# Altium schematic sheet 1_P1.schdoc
size 309 x 223 mm; Symbol: Sheet-Symbol_A4; Device: Sheet-Symbol_A4; @Page Name: P1; @Create Date: 2023-06-11; @Page Count: 1; @Page No: 1; @Project Name: 工业检测; @Schematic Name: Schematic1; @Update Date: 2023-06-11; Company: 嘉立创EDA; Page Size: A4; Version: V1.0
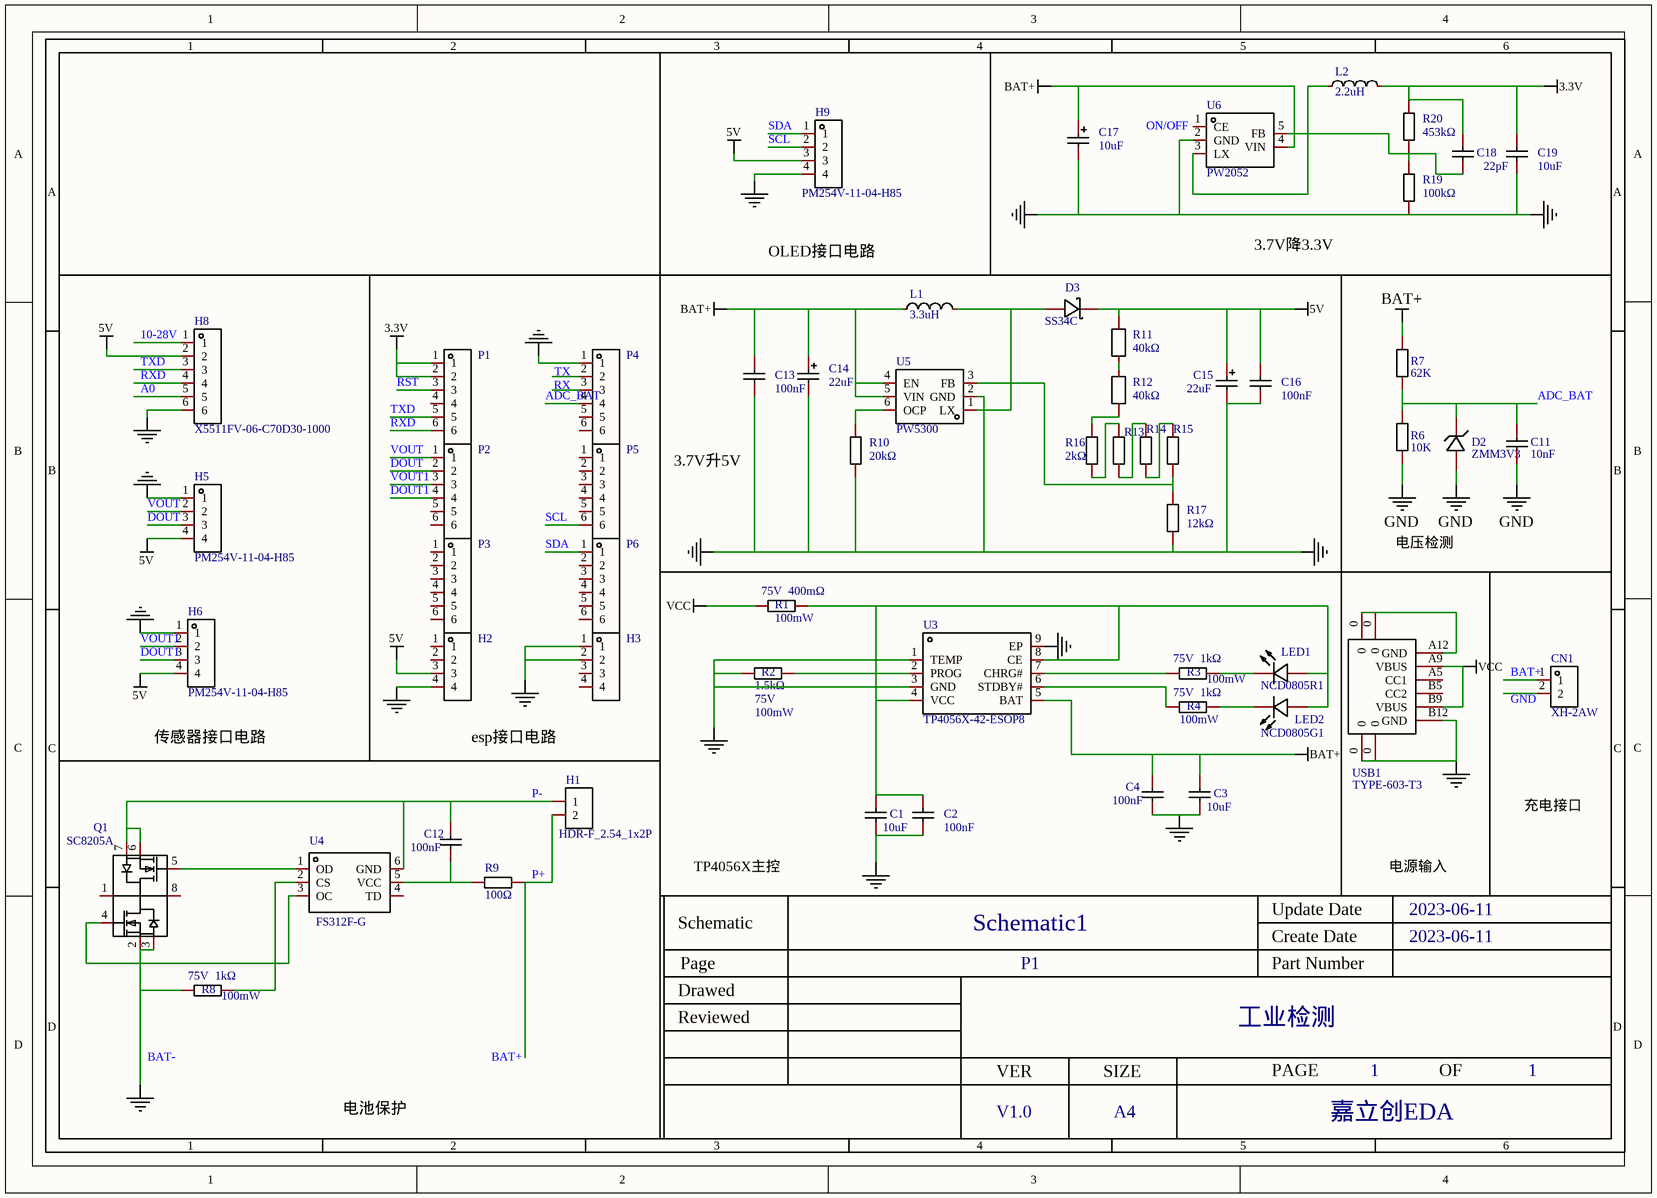
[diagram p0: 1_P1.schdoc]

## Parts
C1  10uF  [C1206]
C2  100nF  [C0603]
C3  10uF  [C1206]
C4  100nF  [C0603]
C11  10nF  [C0603]
C12  100nF  [C0603]
C13  100nF  [C0603]
C14  22uF  [CASE-B_3528]
C15  22uF  [CASE-B_3528]
C16  100nF  [C0603]
C17  10uF  [CAP-SMD_L3.5-W2.8-R-RD]
C18  22pF  [C0603]
C19  10uF  [C1206]
CN1  XH-2AW  [CONN-TH_XH-2AW_C2908611]
D2  ZMM3V3  [LL-34_L3.5-W1.5-RD]
D3  SS34C  [SMC_L7.1-W6.2-LS8.1-R-RD]
H1  HDR-F_2.54_1x2P  [HDR-TH_2P-P2.54-V-F]
H2  2.54-1*4P母  [HDR-TH_4P-P2.54-V-F]  (value not drawn)
H3  2.54-1*4P母  [HDR-TH_4P-P2.54-V-F]  (value not drawn)
H5  PM254V-11-04-H85  [HDR-TH_4P-P2.54-V-F]
H6  PM254V-11-04-H85  [HDR-TH_4P-P2.54-V-F]
H8  X5511FV-06-C70D30-1000  [HDR-TH_6P-P2.54-V-F-3]
H9  PM254V-11-04-H85  [HDR-TH_4P-P2.54-V-F]
L1  3.3uH  [IND-SMD_L5.4-W5.2]
L2  2.2uH  [IND-SMD_L4.4-W4.2]
LED1  NCD0805R1  [LED0805-RD_RED]
LED2  NCD0805G1  [LED0805-R-RD]
P1  2.54-1*6P母  [HDR-TH_6P-P2.54-V-F]  (value not drawn)
P2  2.54-1*6P母  [HDR-TH_6P-P2.54-V-F]  (value not drawn)
P3  2.54-1*6P母  [HDR-TH_6P-P2.54-V-F]  (value not drawn)
P4  2.54-1*6P母  [HDR-TH_6P-P2.54-V-F]  (value not drawn)
P5  2.54-1*6P母  [HDR-TH_6P-P2.54-V-F]  (value not drawn)
P6  2.54-1*6P母  [HDR-TH_6P-P2.54-V-F]  (value not drawn)
Q1  SC8205A  [TSSOP-8_L4.4-W3.0-P0.65-LS6.4-BL]
R1  Power(Watts): 100mW  Overload Voltage (Max): 75V  [R0603]  (hidden comment: 400mΩ)
R2  Power(Watts): 100mW  Overload Voltage (Max): 75V  [R0603]  (hidden comment: 1.5kΩ)
R3  Power(Watts): 100mW  Overload Voltage (Max): 75V  [R0603]  (hidden comment: 1kΩ)
R4  Power(Watts): 100mW  Overload Voltage (Max): 75V  [R0603]  (hidden comment: 1kΩ)
R6  10K  [R0603]
R7  62K  [R0603]
R8  Power(Watts): 100mW  Overload Voltage (Max): 75V  [R0603]  (hidden comment: 1kΩ)
R9  100Ω  [R0603]
R10  20kΩ  [R0603]
R11  40kΩ  [R0603]
R12  40kΩ  [R0603]
R13  2kΩ  [R0603]  (value not drawn)
R14  2kΩ  [R0603]  (value not drawn)
R15  2kΩ  [R0603]  (value not drawn)
R16  2kΩ  [R0603]
R17  12kΩ  [R0603]
R19  100kΩ  [R0603]
R20  453kΩ  [R0603]
U3  TP4056X-42-ESOP8  [SOP-8_L4.9-W3.9-P1.27-LS6.0-TL-EP]
U4  FS312F-G  [SOT-23-6_L2.9-W1.6-P0.95-LS2.8-BR]
U5  PW5300  [SOT-23-6_L2.9-W1.6-P0.95-LS2.8-BL]
U6  PW2052  [SOT-23-5_L2.9-W1.6-P0.95-LS2.8-BL]
USB1  TYPE-603-T3  [USB-C-SMD_TYPE-603-T3]

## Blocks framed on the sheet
OLED接口电路: H9
3.7V降3.3V: C17-C19 L2 R19 R20 U6
传感器接口电路: H5 H6 H8
esp接口电路: H2 H3 P1-P6
3.7V升5V: C13-C16 D3 L1 R10-R17 U5
电压检测: C11 D2 R6 R7
TP4056X主控: C1-C4 LED1 LED2 R1-R4 U3
电源输入: USB1
充电接口: CN1
电池保护: C12 H1 Q1 R8 R9 U4

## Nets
3.3V: C18.2 C19.2 L2.2 P1.1 P1.2 R20.2
5V: C15.1 C16.2 D3.2(K) H2.3 H5.4 H6.4 H8.2 H9.3 R11.2
BAT+: C3.2 C4.2 C13.2 C14.1 C17.1 L1.1 R7.2 U3.5(BAT) U5.4(EN) U5.5(VIN) U6.4(VIN)
GND: C11.1 D2.2(A) R6.1
NetC1_1: C1.1 C2.1 C3.1 C4.1 C13.1 C14.2 C15.2 C16.1 C17.2 C19.1 H2.4 H3.1 H3.2 H5.1 H6.1 H8.6 H9.4 P4.1 Q1.2(S1) Q1.3(S1) R2.1 R8.1 R10.1 R17.1 R19.1 U3.1(TEMP) U3.3(GND) U3.9(EP) U5.2(GND) U6.2(GND) USB1.0 USB1.B12(GND)
VCC: R1.1 USB1.A9(VBUS) USB1.B9(VBUS)
ADC_BAT: C11.2 D2.1(C) P4.4 R6.2 R7.1
DOUT: P2.2
DOUT1: P2.4
RXD: P1.6
SCL: P5.6
SDA: P6.1
TXD: P1.5
VOUT: P2.1
VOUT1: P2.3
NetC1_2: C1.2 C2.2 LED1.2(+) LED2.1(A) R1.2 U3.4(VCC) U3.8(CE)
NetC12_1: C12.1 R9.1 U4.5(VCC)
NetC12_2: C12.2 H1.1 Q1.6(S2) Q1.7(S2) U4.6(GND)
NetC18_1: C18.1 R19.2 R20.1 U6.5(FB)
NetD3_1: D3.1(A) L1.2 U5.1(LX)
NetH1_2: H1.2 R9.2
NetL2_1: L2.1 U6.3(LX)
NetLED1_1: LED1.1(-) R3.2
NetLED2_2: LED2.2(K) R4.2
NetQ1_4: Q1.4(G1) U4.3(OC)
NetQ1_5: Q1.5(G2) U4.1(OD)
NetR2_2: R2.2 U3.2(PROG)
NetR3_1: R3.1 U3.7(CHRG#)
NetR4_1: R4.1 U3.6(STDBY#)
NetR8_2: R8.2 U4.2(CS)
NetR10_2: R10.2 U5.6(OCP)
NetR11_1: R11.1 R12.2
NetR12_1: R12.1 R16.2
NetR13_1: R13.1 R14.2
NetR13_2: R13.2 R16.1
NetR14_1: R14.1 R15.2
NetR15_1: R15.1 R17.2 U5.3(FB)
NetUSB1_0: USB1.0 USB1.A12(GND)

Not connected (* = marked no-connect by the designer): CN1 1 2; H2 1 2; H3 3 4; H5 2 3; H6 2 3; H8 1 3 4 5; H9 1 2; P1 3 4; P2 5 6; P3 1 2 3 4 5 6; P4 2 3 5 6; P5 1 2 3 4 5; P6 2 3 4 5 6; Q1 1(D12) 8(D12); U4 4(TD); U6 1(CE); USB1 A5(CC1) B5(CC2)

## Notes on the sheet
- (near H9) SDA
- (near H9) SCL
- (near U6) ON/OFF
- (near H8) 10-28V
- (near H8) A0
- (near H8) TXD
- (near H8) RXD
- (near P1) RST
- (near P4) TX
- (near P4) RX
- (near H5) VOUT
- (near H5) DOUT
- (near H6) VOUT1
- (near H6) DOUT1
- (near CN1) BAT+
- (near CN1) GND
- (near H1) P-
- (near R9) P+
- BAT-
- BAT+

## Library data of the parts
C1 C3 C19 = CL31A106KBHNNNE: 容值:10uF;精度:±10%;额定电压:50V;材质(温度系数):X5R;; Manufacturer: SAMSUNG(三星); Add into BOM: yes; Tolerance: ±10%; Voltage Rated: 50V; Temperature Coefficient: X5R
C2 C4 C12 C13 C16 = CC0603KRX7R8BB104: 容值:100nF;精度:±10%;额定电压:25V;材质(温度系数):X7R;; Manufacturer: YAGEO(国巨); Add into BOM: yes; Tolerance: ±10%; Voltage Rated: 25V; Temperature Coefficient: X7R
C11 = 0603B103K500NT: Manufacturer: FH; Convert to PCB: yes
C14 C15 = TAJB226K016RNJ: 容值:22uF;精度:±10%;额定电压:16V;等效串联电阻:2.3Ω@100kHz;工作温度:-55℃~+125℃;; Manufacturer: Kyocera AVX; Add into BOM: yes; Tolerance: ±10%; Rated Voltage: 16V
C17 = TAJB106K025RNJ: 容值:10uF;精度:±10%;额定电压:25V;等效串联电阻:2.5Ω@100kHz;; Manufacturer: Kyocera AVX; Add into BOM: yes; Tolerance: ±10%; Rated Voltage: 25V
C18 = CL10C220JB8NNNC: 容值:22pF;精度:±5%;额定电压:50V;材质(温度系数):C0G;; Manufacturer: SAMSUNG(三星); Add into BOM: yes; Tolerance: ±5%; Voltage Rated: 50V; Temperature Coefficient: C0G
CN1 = XH-2AW_C2908611: 参考系列:XH;间距:2.54mm;插针结构:1x2P;排数:1;每排PIN数:2;行距:-;公母:公型插针;安装方式:弯插;额定电流:3A;工作温度范围:-25℃~+85℃;; Manufacturer: HCTL(华灿天禄); Add into BOM: yes; Reference Series: XH; Pitch: 2.54mm; Pins Structure: 1x2P; Number of PINs Per Row: 2; Gender: 公型插针; Current Rating (Max): 3A
D2 = ZMM3V3: Manufacturer: SEMTECH; Convert to PCB: yes
D3 = SS34C_C13763: 直流反向耐压(Vr):40V;平均整流电流(Io):3A;正向压降(Vf):500mV@3A;; Manufacturer: MDD; Symbol: SS34; Add into BOM: yes; Reverse Voltage (Vr): 40V; Average Rectified Current (Io): 3A
H1 = HDR-F_2.54_1x2P: Symbol: Header-Female-2.54_1x2; Convert to PCB: yes
H2 H3 = 2.54-1*4P母: 排数:单排;总孔位数:4;间距:2.54mm;插孔结构:1x4P;行距:-;安装类型:直插;圆孔/方孔:方孔;额定电流:3A;额定电压:-;插孔方向:顶部;塑高:-;触头材质:青铜;触头镀层:-;工作温度范围:-40℃~+105℃;焊接温度(最大值):-;; Manufacturer: BOOMELE(博穆精密); Add into BOM: yes; Number of Holes: 4; Pitch: 2.54mm; Holes Structure: 1x4P; Circular Hole / Square Hole: 方孔; Current Rating (Max): 3A; Holes Direction: 顶部
H5 H6 H9 = PM254V-11-04-H85: 排数:单排;总孔位数:4;间距:2.54mm;插孔结构:1x4P;行距:-;安装类型:直插;塑高:-;触头材质:黄铜;触头镀层:-;; Manufacturer: XFCN(兴飞); Add into BOM: yes; Number of Holes: 4; Pitch: 2.54mm; Holes Structure: 1x4P
H8 = X5511FV-06-C70D30-1000: 排数:单排;总孔位数:6;间距:2.54mm;插孔结构:1x6P;行距:-;安装类型:直插;圆孔/方孔:圆孔;额定电流:3A;额定电压:-;插孔方向:顶部;塑高:7mm;触头材质:黄铜;触头镀层:金;工作温度范围:-40℃~+105℃;焊接温度(最大值):260℃;; Manufacturer: XKB Connectivity(中国星坤); Add into BOM: yes; Number of Holes: 6; Pitch: 2.54mm; Holes Structure: 1x6P; Circular Hole / Square Hole: 圆孔; Current Rating (Max): 3A; Holes Direction: 顶部; Welding Temperature (Max): 260℃
L1 = MWSA0503S-3R3MT: 额定电流:5.5A;精度:±20%;电感值:3.3uH;直流电阻(DCR):38mΩ;; Manufacturer: Sunlord(顺络); Add into BOM: yes; Rated Current: 5.5A; Tolerance: ±20%; DC Resistance (DCR): 38mΩ
L2 = MWSA0402S-2R2MT: 电感值:2.2uH;精度:±20%;额定电流:4.5A;直流电阻(DCR):58mΩ;; Manufacturer: Sunlord(顺络); Add into BOM: yes; Tolerance: ±20%; Rated Current: 4.5A; DC Resistance (DCR): 58mΩ
LED1 = NCD0805R1: 发光颜色:红灯;; Manufacturer: 国星光电; Symbol: FC-2012HRK-620D; Add into BOM: yes; Emitted Color: 红灯
LED2 = NCD0805G1: 发光颜色:翠绿;; Manufacturer: 国星光电; Symbol: FC-2012UGK-520D5; Add into BOM: yes; Emitted Color: 翠绿
P1-P6 = 2.54-1*6P母: 排数:单排;总孔位数:6;间距:2.54mm;插孔结构:1x6P;行距:-;安装类型:直插;塑高:-;触头材质:-;触头镀层:-;; Manufacturer: BOOMELE(博穆精密); Symbol: Header-Female-2.54_1x6; Add into BOM: yes; Number of Holes: 6; Pitch: 2.54mm; Holes Structure: 1x6P
Q1 = SC8205A: 类型:N沟道;漏源电压(Vdss):20V;连续漏极电流(Id):6A;功率(Pd):2W;导通电阻(RDS(on)@Vgs,Id):25mΩ@10V,5A;阈值电压(Vgs(th)@Id):1.5V@250uA;; Manufacturer: FM(富满); Add into BOM: yes; Type: N沟道; Drain Source Voltage (Vdss): 20V; Continuous Drain Current (Id): 6A; Power Dissipation (Pd): 2W
R1 = 0603WAF400LT5E: 电阻类型:厚膜电阻;阻值:400mΩ;精度:±1%;功率:100mW;; Manufacturer: UNI-ROYAL(厚声); Add into BOM: yes; Tolerance: ±1%; Temperature Coefficient: ±800ppm/℃
R2 = 0603WAF1501T5E: 电阻类型:厚膜电阻;阻值:1.5kΩ;精度:±1%;功率:100mW;; Manufacturer: UNI-ROYAL(厚声); Add into BOM: yes; Tolerance: ±1%; Temperature Coefficient: ±100ppm/℃
R3 R4 R8 = RT0603BRD071KL: 电阻类型:薄膜电阻;阻值:1kΩ;精度:±0.1%;功率:100mW;; Manufacturer: YAGEO(国巨); Add into BOM: yes; Tolerance: ±0.1%; Temperature Coefficient: ±25ppm/℃
R6 = 0603WAF1002T5E: Manufacturer: UniOhm; Convert to PCB: yes
R7 = 0603WAF6202T5E: Manufacturer: UniOhm; Convert to PCB: yes
R9 = 0603WAF1000T5E: 电阻类型:厚膜电阻;阻值:100Ω;精度:±1%;功率:100mW;; Manufacturer: UNI-ROYAL(厚声); Add into BOM: yes; Tolerance: ±1%; Power(Watts): 100mW; Temperature Coefficient: ±200ppm/℃; Overload Voltage (Max): 75V
R10 = AC0603FR-0720KL: 电阻类型:厚膜电阻;阻值:20kΩ;精度:±1%;功率:100mW;; Manufacturer: YAGEO(国巨); Add into BOM: yes; Tolerance: ±1%; Power(Watts): 100mW; Temperature Coefficient: ±100ppm/℃; Overload Voltage (Max): 75V
R11 R12 = SCR0603F40K: 阻值:40kΩ;精度:±1%;; Manufacturer: VO(翔胜); Add into BOM: yes; Tolerance: ±1%
R13-R16 = AC0603FR-072KL: 电阻类型:厚膜电阻;阻值:2kΩ;精度:±1%;功率:100mW;; Manufacturer: YAGEO(国巨); Add into BOM: yes; Tolerance: ±1%; Power(Watts): 100mW; Temperature Coefficient: ±100ppm/℃; Overload Voltage (Max): 75V
R17 = 0603WAF1202T5E: 电阻类型:厚膜电阻;阻值:12kΩ;精度:±1%;功率:100mW;; Manufacturer: UNI-ROYAL(厚声); Add into BOM: yes; Tolerance: ±1%; Power(Watts): 100mW; Temperature Coefficient: ±100ppm/℃; Overload Voltage (Max): 75V
R19 = RT0603BRD07100KL: 电阻类型:薄膜电阻;阻值:100kΩ;精度:±0.1%;功率:100mW;; Manufacturer: YAGEO(国巨); Add into BOM: yes; Tolerance: ±0.1%; Power(Watts): 100mW; Temperature Coefficient: ±25ppm/℃; Overload Voltage (Max): 75V
R20 = 0603WAF4533T5E: 电阻类型:厚膜电阻;阻值:453kΩ;精度:±1%;功率:100mW;; Manufacturer: UNI-ROYAL(厚声); Add into BOM: yes; Tolerance: ±1%; Power(Watts): 100mW; Temperature Coefficient: ±100ppm/℃; Overload Voltage (Max): 75V
U3 = TP4056X-42-ESOP8: Manufacturer: TOPPOWER(南京拓微); Symbol: TP4056X_C2763448; Add into BOM: yes
U4 = FS312F-G: 单节锂离子/聚合物电池保护芯片; Manufacturer: FORTUNE(富晶); Add into BOM: yes
U5 = PW5300: Add into BOM: yes
U6 = PW2052: Add into BOM: yes
USB1 = TYPE-603-T3: Manufacturer: Yuandi(台湾元迪); Convert to PCB: yes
